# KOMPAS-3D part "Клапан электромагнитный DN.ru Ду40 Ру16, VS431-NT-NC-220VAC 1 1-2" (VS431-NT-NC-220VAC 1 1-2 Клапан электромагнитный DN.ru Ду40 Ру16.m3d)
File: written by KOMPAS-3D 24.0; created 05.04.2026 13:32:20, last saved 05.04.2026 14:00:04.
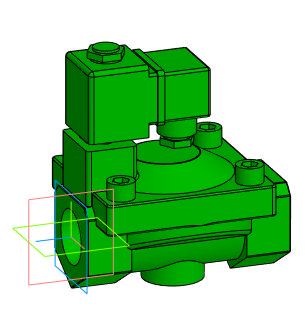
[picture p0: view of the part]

Document properties: Автор: artio; Полное имя файла: C:\Users\artio\OneDrive\Рабочий стол\Клапан электромагнитный DN.ru\VS431\VS431-NT-NC\VS431-NT-NC-220VAC\Ду40\VS431-NT-NC-220VAC 1 1-2 Клапан электромагнитный DN.ru Ду40 Ру16.m3d

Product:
- Body: Тело 1  | qty 1
    Масса: 3.859459
- Part/product: Клапан электромагнитный DN.ru Ду40 Ру16  | designation VS431-NT-NC-220VAC 1 1-2
    Масса: 2.285
    Раздел спецификации: Прочие изделия
    Примечание: D130-04672
    additional columns: ef56311e-7521-43dc-8291-0e6108b3d81d; artio; c; Шероховатость не задана; Да

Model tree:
1. Операция без истории:1

Expressions: VS431-NT-NC-220VAC 1 1-2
